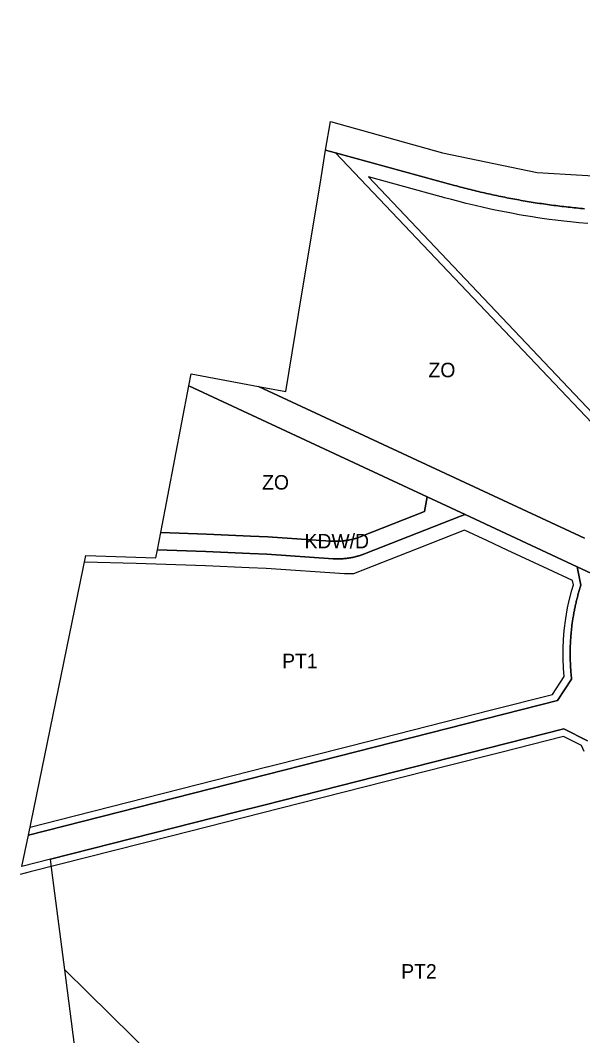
# Model space of a CAD drawing. Extents: x -297746 to -295403, y 27112 to 28877.
# Drawn here: x -297567 to -297178, y 27466 to 28167 of the extents above; entities that cross this region are included whole.
import ezdxf

# ---------------------------------------------------------------- set-up
doc = ezdxf.new("R2010")
doc.units = 0
for name, color, linetype in [('linie_rozgraniczajace', 7, 'Continuous'), ('linie_zabudowy_nieprzekraczalne', 7, 'Continuous'), ('linie_zabudowy_obowiazujace', 7, 'Continuous'), ('oznaczenia_przeznaczen', 7, 'Continuous')]:
    doc.layers.add(name, color=color, linetype=linetype)

msp = doc.modelspace()

# ---------------------------------------------------------------- linework, layer by layer
at = {"layer": 'linie_rozgraniczajace'}
for points in [[(-297352.574, 28097.205), (-297275.154, 28075.397), (-297209.735, 28062.001), (-297116.494, 28056.361), (-297048.036, 28064.682), (-296954.075, 28076.102), (-296853.315, 28078.922), (-296783.197, 28092.318), (-296733.569, 28109.944), (-296648.599, 28167.051)], [(-297176.987, 28036.903), (-297178.41, 28037.03), (-297179.832, 28037.161), (-297181.254, 28037.296), (-297182.676, 28037.435), (-297184.097, 28037.579), (-297185.517, 28037.726), (-297186.938, 28037.877), (-297188.357, 28038.032), (-297189.777, 28038.191), (-297191.196, 28038.354), (-297192.614, 28038.521), (-297194.032, 28038.692), (-297195.45, 28038.867), (-297196.867, 28039.046), (-297198.283, 28039.229), (-297199.699, 28039.416), (-297201.115, 28039.607), (-297202.53, 28039.802), (-297203.944, 28040), (-297205.358, 28040.203), (-297206.771, 28040.41), (-297208.184, 28040.621), (-297209.596, 28040.835), (-297211.007, 28041.054), (-297212.418, 28041.276), (-297213.828, 28041.503), (-297215.238, 28041.733), (-297216.647, 28041.967), (-297218.055, 28042.206), (-297219.463, 28042.448), (-297220.87, 28042.694), (-297222.276, 28042.944), (-297223.681, 28043.198), (-297225.086, 28043.456), (-297226.49, 28043.718), (-297227.894, 28043.984), (-297229.296, 28044.254), (-297230.698, 28044.528), (-297232.099, 28044.805), (-297233.499, 28045.087), (-297234.899, 28045.372), (-297236.297, 28045.662), (-297237.695, 28045.955), (-297239.092, 28046.252), (-297240.488, 28046.553), (-297241.884, 28046.859), (-297243.278, 28047.167), (-297244.672, 28047.48), (-297246.065, 28047.797), (-297247.456, 28048.118), (-297248.847, 28048.442), (-297250.237, 28048.771), (-297251.626, 28049.103), (-297253.015, 28049.439), (-297254.402, 28049.78), (-297255.788, 28050.124), (-297257.173, 28050.471), (-297258.558, 28050.823), (-297259.941, 28051.179), (-297261.323, 28051.538), (-297262.704, 28051.902), (-297264.085, 28052.269), (-297265.464, 28052.64), (-297266.842, 28053.015), (-297348.943, 28075.477), (-297355.848, 28077.366), (-297352.574, 28097.205)], [(-297177, 27809.324), (-297402.243, 27914.223), (-297383.34, 27910.754), (-297372.231, 27978.076), (-297364.965, 28022.112), (-297359.02, 28058.141), (-297355.848, 28077.366), (-297348.943, 28075.477), (-297133.128, 27848.059)], [(-297133.128, 27848.059), (-297348.943, 28075.477), (-297266.842, 28053.015), (-297265.464, 28052.64), (-297264.085, 28052.269), (-297262.704, 28051.902), (-297261.323, 28051.538), (-297259.941, 28051.179), (-297258.558, 28050.823), (-297257.173, 28050.471), (-297255.788, 28050.124), (-297254.402, 28049.78), (-297253.015, 28049.439), (-297251.626, 28049.103), (-297250.237, 28048.771), (-297248.847, 28048.442), (-297247.456, 28048.118), (-297246.065, 28047.797), (-297244.672, 28047.48), (-297243.278, 28047.167), (-297241.884, 28046.859), (-297240.488, 28046.553), (-297239.092, 28046.252), (-297237.695, 28045.955), (-297236.297, 28045.662), (-297234.899, 28045.372), (-297233.499, 28045.087), (-297232.099, 28044.805), (-297230.698, 28044.528), (-297229.296, 28044.254), (-297227.894, 28043.984), (-297226.49, 28043.718), (-297225.086, 28043.456), (-297223.681, 28043.198), (-297222.276, 28042.944), (-297220.87, 28042.694), (-297219.463, 28042.448), (-297218.055, 28042.206), (-297216.647, 28041.967), (-297215.238, 28041.733), (-297213.828, 28041.503), (-297212.418, 28041.276), (-297211.007, 28041.054), (-297209.596, 28040.835), (-297208.184, 28040.621), (-297206.771, 28040.41), (-297205.358, 28040.203), (-297203.944, 28040), (-297202.53, 28039.802), (-297201.115, 28039.607), (-297199.699, 28039.416), (-297198.283, 28039.229), (-297196.867, 28039.046), (-297195.45, 28038.867), (-297194.032, 28038.692), (-297192.614, 28038.521), (-297191.196, 28038.354), (-297189.777, 28038.191), (-297188.357, 28038.032), (-297186.938, 28037.877), (-297185.517, 28037.726), (-297184.097, 28037.579), (-297182.676, 28037.435), (-297181.254, 28037.296), (-297179.832, 28037.161), (-297178.41, 28037.03), (-297176.987, 28036.903)], [(-297152.791, 27775.987), (-297181.991, 27789.586), (-297259.566, 27825.714), (-297285.818, 27837.94), (-297450.331, 27914.556), (-297448.76, 27922.76), (-297402.243, 27914.223), (-297177, 27809.324)], [(-297347.308, 27795.043), (-297347.755, 27795.046), (-297348.202, 27795.052), (-297348.649, 27795.063), (-297349.096, 27795.078), (-297349.543, 27795.096), (-297349.99, 27795.119), (-297350.436, 27795.145), (-297350.68, 27795.161), (-297396.449, 27798.31), (-297408.328, 27798.853), (-297438.575, 27800.185), (-297472.022, 27801.277), (-297469.737, 27813.209), (-297438.115, 27812.176), (-297407.79, 27810.841), (-297395.763, 27810.291), (-297352.553, 27807.318), (-297352.31, 27807.302), (-297351.863, 27807.276), (-297351.416, 27807.253), (-297350.97, 27807.235), (-297350.523, 27807.22), (-297350.076, 27807.21), (-297349.628, 27807.203), (-297349.181, 27807.201), (-297348.734, 27807.202), (-297348.287, 27807.208), (-297347.84, 27807.217), (-297347.393, 27807.23), (-297346.946, 27807.248), (-297346.499, 27807.269), (-297346.053, 27807.295), (-297345.606, 27807.324), (-297345.16, 27807.358), (-297344.715, 27807.395), (-297344.27, 27807.437), (-297343.825, 27807.482), (-297343.38, 27807.531), (-297342.936, 27807.585), (-297342.493, 27807.642), (-297342.05, 27807.703), (-297341.607, 27807.768), (-297341.165, 27807.838), (-297340.724, 27807.911), (-297340.284, 27807.988), (-297339.844, 27808.069), (-297339.405, 27808.154), (-297338.966, 27808.243), (-297338.529, 27808.335), (-297338.092, 27808.432), (-297337.657, 27808.533), (-297337.222, 27808.637), (-297336.788, 27808.746), (-297336.355, 27808.858), (-297335.923, 27808.974), (-297335.492, 27809.094), (-297335.063, 27809.218), (-297334.634, 27809.345), (-297334.206, 27809.477), (-297333.78, 27809.612), (-297333.355, 27809.751), (-297332.931, 27809.894), (-297332.509, 27810.041), (-297332.088, 27810.191), (-297331.668, 27810.346), (-297331.25, 27810.504), (-297330.833, 27810.665), (-297287.504, 27827.693), (-297285.818, 27837.94), (-297259.566, 27825.714), (-297262.647, 27824.569), (-297328.959, 27798.508), (-297329.376, 27798.346), (-297329.795, 27798.188), (-297330.215, 27798.034), (-297330.636, 27797.884), (-297331.058, 27797.737), (-297331.482, 27797.594), (-297331.907, 27797.455), (-297332.333, 27797.32), (-297332.761, 27797.188), (-297333.189, 27797.06), (-297333.619, 27796.937), (-297334.05, 27796.817), (-297334.482, 27796.701), (-297334.915, 27796.588), (-297335.348, 27796.48), (-297335.783, 27796.375), (-297336.219, 27796.275), (-297336.656, 27796.178), (-297337.093, 27796.085), (-297337.531, 27795.996), (-297337.971, 27795.912), (-297338.41, 27795.831), (-297338.851, 27795.753), (-297339.292, 27795.68), (-297339.734, 27795.611), (-297340.176, 27795.546), (-297340.619, 27795.485)], [(-297561.228, 27604.259), (-297521.53, 27797.34), (-297473.092, 27795.69), (-297472.022, 27801.277), (-297438.575, 27800.185), (-297408.328, 27798.853), (-297396.449, 27798.31), (-297350.68, 27795.161), (-297350.436, 27795.145), (-297349.99, 27795.119), (-297349.543, 27795.096), (-297349.096, 27795.078), (-297348.649, 27795.063), (-297348.202, 27795.052), (-297347.755, 27795.046), (-297347.308, 27795.043), (-297346.861, 27795.045), (-297346.414, 27795.05), (-297345.966, 27795.06), (-297345.519, 27795.073), (-297345.073, 27795.091), (-297344.626, 27795.112), (-297344.179, 27795.138), (-297343.733, 27795.167), (-297343.287, 27795.2), (-297342.842, 27795.238), (-297342.396, 27795.279), (-297341.951, 27795.325), (-297341.507, 27795.374), (-297341.063, 27795.427), (-297340.619, 27795.485), (-297340.176, 27795.546), (-297339.734, 27795.611), (-297339.292, 27795.68), (-297338.851, 27795.753), (-297338.41, 27795.831), (-297337.971, 27795.912), (-297337.531, 27795.996), (-297337.093, 27796.085), (-297336.656, 27796.178), (-297336.219, 27796.275), (-297335.783, 27796.375), (-297335.348, 27796.48), (-297334.915, 27796.588), (-297334.482, 27796.701), (-297334.05, 27796.817), (-297333.619, 27796.937), (-297333.189, 27797.06), (-297332.761, 27797.188), (-297332.333, 27797.32), (-297331.907, 27797.455), (-297331.482, 27797.594), (-297331.058, 27797.737), (-297330.636, 27797.884), (-297330.215, 27798.034), (-297329.795, 27798.188), (-297329.376, 27798.346), (-297328.959, 27798.508), (-297262.647, 27824.569), (-297259.566, 27825.714), (-297181.991, 27789.586), (-297179.498, 27776.965), (-297179.736, 27776.217), (-297179.971, 27775.467), (-297180.202, 27774.716), (-297180.429, 27773.963), (-297180.652, 27773.21), (-297180.872, 27772.455), (-297181.088, 27771.7), (-297181.299, 27770.943), (-297181.507, 27770.185), (-297181.711, 27769.426), (-297181.911, 27768.666), (-297182.108, 27767.905), (-297182.3, 27767.144), (-297182.489, 27766.381), (-297182.673, 27765.617), (-297182.854, 27764.852), (-297183.031, 27764.087), (-297183.204, 27763.32), (-297183.373, 27762.553), (-297183.538, 27761.784), (-297183.699, 27761.015), (-297183.857, 27760.245), (-297184.01, 27759.475), (-297184.159, 27758.703), (-297184.305, 27757.931), (-297184.447, 27757.158), (-297184.584, 27756.384), (-297184.718, 27755.61), (-297184.848, 27754.835), (-297184.974, 27754.059), (-297185.096, 27753.283), (-297185.214, 27752.506), (-297185.328, 27751.729), (-297185.438, 27750.951), (-297185.544, 27750.172), (-297185.646, 27749.393), (-297185.744, 27748.613), (-297185.838, 27747.833)], [(-297340.619, 27795.485), (-297341.063, 27795.427), (-297341.507, 27795.374), (-297341.951, 27795.325), (-297342.396, 27795.279), (-297342.842, 27795.238), (-297343.287, 27795.2), (-297343.733, 27795.167), (-297344.179, 27795.138), (-297344.626, 27795.112), (-297345.073, 27795.091), (-297345.519, 27795.073), (-297345.966, 27795.06), (-297346.414, 27795.05), (-297346.861, 27795.045), (-297347.308, 27795.043)], [(-297191.301, 27677.639), (-297398.591, 27624.957), (-297418.041, 27620.014), (-297545.905, 27587.518), (-297565.705, 27582.486), (-297561.228, 27604.259), (-297195.737, 27697.147), (-297185.88, 27711.971), (-297185.946, 27712.549), (-297186.031, 27713.33), (-297186.112, 27714.112), (-297186.19, 27714.894), (-297186.263, 27715.676), (-297186.333, 27716.459), (-297186.398, 27717.242), (-297186.46, 27718.025), (-297186.518, 27718.809), (-297186.571, 27719.593), (-297186.621, 27720.377), (-297186.666, 27721.162), (-297186.708, 27721.946), (-297186.745, 27722.731), (-297186.779, 27723.516), (-297186.809, 27724.302), (-297186.834, 27725.087), (-297186.856, 27725.872), (-297186.873, 27726.658), (-297186.887, 27727.444), (-297186.897, 27728.23), (-297186.902, 27729.015), (-297186.904, 27729.801), (-297186.902, 27730.587), (-297186.895, 27731.373), (-297186.885, 27732.158), (-297186.87, 27732.944), (-297186.852, 27733.73), (-297186.83, 27734.515), (-297186.803, 27735.301), (-297186.773, 27736.086), (-297186.738, 27736.871), (-297186.7, 27737.656), (-297186.658, 27738.44), (-297186.611, 27739.225), (-297186.561, 27740.009), (-297186.507, 27740.793), (-297186.448, 27741.577), (-297186.386, 27742.36), (-297186.32, 27743.143), (-297186.249, 27743.926), (-297186.175, 27744.708), (-297186.097, 27745.49), (-297186.014, 27746.271), (-297185.928, 27747.052), (-297185.838, 27747.833), (-297185.744, 27748.613), (-297185.646, 27749.393), (-297185.544, 27750.172), (-297185.438, 27750.951), (-297185.328, 27751.729), (-297185.214, 27752.506), (-297185.096, 27753.283), (-297184.974, 27754.059), (-297184.848, 27754.835), (-297184.718, 27755.61), (-297184.584, 27756.384), (-297184.447, 27757.158), (-297184.305, 27757.931), (-297184.159, 27758.703), (-297184.01, 27759.475), (-297183.857, 27760.245), (-297183.699, 27761.015), (-297183.538, 27761.784), (-297183.373, 27762.553), (-297183.204, 27763.32), (-297183.031, 27764.087), (-297182.854, 27764.852), (-297182.673, 27765.617), (-297182.489, 27766.381), (-297182.3, 27767.144), (-297182.108, 27767.905), (-297181.911, 27768.666), (-297181.711, 27769.426), (-297181.507, 27770.185), (-297181.299, 27770.943), (-297181.088, 27771.7), (-297180.872, 27772.455), (-297180.652, 27773.21), (-297180.429, 27773.963), (-297180.202, 27774.716), (-297179.971, 27775.467), (-297179.736, 27776.217), (-297179.498, 27776.965), (-297181.991, 27789.586), (-297152.791, 27775.987)], [(-297185.838, 27747.833), (-297185.928, 27747.052), (-297186.014, 27746.271), (-297186.097, 27745.49), (-297186.175, 27744.708), (-297186.249, 27743.926), (-297186.32, 27743.143), (-297186.386, 27742.36), (-297186.448, 27741.577), (-297186.507, 27740.793), (-297186.561, 27740.009), (-297186.611, 27739.225), (-297186.658, 27738.44), (-297186.7, 27737.656), (-297186.738, 27736.871), (-297186.773, 27736.086), (-297186.803, 27735.301), (-297186.83, 27734.515), (-297186.852, 27733.73), (-297186.87, 27732.944), (-297186.885, 27732.158), (-297186.895, 27731.373), (-297186.902, 27730.587), (-297186.904, 27729.801), (-297186.902, 27729.015), (-297186.897, 27728.23), (-297186.887, 27727.444), (-297186.873, 27726.658), (-297186.856, 27725.872), (-297186.834, 27725.087), (-297186.809, 27724.302), (-297186.779, 27723.516), (-297186.745, 27722.731), (-297186.708, 27721.946), (-297186.666, 27721.162), (-297186.621, 27720.377), (-297186.571, 27719.593), (-297186.518, 27718.809), (-297186.46, 27718.025), (-297186.398, 27717.242), (-297186.333, 27716.459), (-297186.263, 27715.676), (-297186.19, 27714.894), (-297186.112, 27714.112), (-297186.031, 27713.33), (-297185.946, 27712.549), (-297185.88, 27711.971), (-297195.737, 27697.147), (-297561.228, 27604.259)], [(-297379.62, 27357.248), (-297536.097, 27511.179), (-297544.93, 27579.93), (-297545.905, 27587.518), (-297418.041, 27620.014), (-297398.591, 27624.957), (-297191.301, 27677.639), (-297175.004, 27669.361)], [(-297175.004, 27669.361), (-297191.301, 27677.639)]]:
    msp.add_lwpolyline(points, dxfattribs=at)
for points in [[(-297349.181, 27807.201), (-297349.628, 27807.203), (-297350.076, 27807.21), (-297350.523, 27807.22), (-297350.97, 27807.235), (-297351.416, 27807.253), (-297351.863, 27807.276), (-297352.31, 27807.302), (-297352.553, 27807.318), (-297395.763, 27810.291), (-297407.79, 27810.841), (-297438.115, 27812.176), (-297469.737, 27813.209), (-297450.331, 27914.556), (-297285.818, 27837.94), (-297287.504, 27827.693), (-297330.833, 27810.665), (-297331.25, 27810.504), (-297331.668, 27810.346), (-297332.088, 27810.191), (-297332.509, 27810.041), (-297332.931, 27809.894), (-297333.355, 27809.751), (-297333.78, 27809.612), (-297334.206, 27809.477), (-297334.634, 27809.345), (-297335.063, 27809.218), (-297335.492, 27809.094), (-297335.923, 27808.974), (-297336.355, 27808.858), (-297336.788, 27808.746), (-297337.222, 27808.637), (-297337.657, 27808.533), (-297338.092, 27808.432), (-297338.529, 27808.335), (-297338.966, 27808.243), (-297339.405, 27808.154), (-297339.844, 27808.069), (-297340.284, 27807.988), (-297340.724, 27807.911), (-297341.165, 27807.838), (-297341.607, 27807.768), (-297342.05, 27807.703), (-297342.493, 27807.642), (-297342.936, 27807.585), (-297343.38, 27807.531), (-297343.825, 27807.482), (-297344.27, 27807.437), (-297344.715, 27807.395), (-297345.16, 27807.358), (-297345.606, 27807.324), (-297346.053, 27807.295), (-297346.499, 27807.269), (-297346.946, 27807.248), (-297347.393, 27807.23), (-297347.84, 27807.217), (-297348.287, 27807.208), (-297348.734, 27807.202)], [(-297215.315, 27280.215), (-297256.262, 27299.118), (-297370.123, 27306.524), (-297400.878, 27308.022), (-297525.782, 27430.894), (-297536.097, 27511.179), (-297379.62, 27357.248), (-297243.742, 27348.41), (-297194.759, 27325.796), (-297200.803, 27312.318)]]:
    msp.add_lwpolyline(points, close=True, dxfattribs=at)
at = {"layer": 'linie_zabudowy_nieprzekraczalne'}
for points in [[(-297326.341, 28058.929), (-297167.124, 27891.151)], [(-297326.341, 28058.929), (-297167.124, 27891.151)], [(-297174.593, 28026.666), (-297180.884, 28027.218), (-297186.661, 28027.793), (-297191.377, 28028.311), (-297196.969, 28028.982), (-297201.428, 28029.561), (-297207.967, 28030.481), (-297214.429, 28031.473), (-297219.318, 28032.279), (-297222.13, 28032.765), (-297227.506, 28033.737), (-297233.644, 28034.919), (-297239.79, 28036.18), (-297246.759, 28037.703), (-297252.451, 28039.021), (-297258.866, 28040.588), (-297264.458, 28042.025), (-297268.896, 28043.213), (-297273.644, 28044.53), (-297275.754, 28045.131), (-297276.085, 28045.179), (-297326.341, 28058.929)], [(-297230.542, 27801.169), (-297244.109, 27807.488), (-297259.973, 27814.876), (-297292.548, 27802.074), (-297336.572, 27784.772), (-297342.936, 27784.607), (-297397.017, 27788.328), (-297408.773, 27788.865), (-297438.955, 27790.194), (-297486.716, 27791.753), (-297522.451, 27792.85)], [(-297560.106, 27609.705), (-297540.12, 27614.784), (-297396.415, 27651.306), (-297396.26, 27651.346), (-297338.79, 27665.951), (-297242.21, 27690.496)], [(-297235.783, 27661.176), (-297272.33, 27651.888), (-297328.649, 27637.575), (-297387.499, 27622.618), (-297462.51, 27603.555), (-297560.033, 27578.769), (-297566.821, 27577.044)]]:
    msp.add_lwpolyline(points, dxfattribs=at)
at = {"layer": 'linie_zabudowy_obowiazujace'}
for points in [[(-297242.21, 27690.496), (-297199.043, 27701.467), (-297191.033, 27713.708), (-297191.546, 27719.636), (-297191.805, 27726.149), (-297191.79, 27733.246), (-297191.525, 27739.436), (-297191.04, 27745.46), (-297189.979, 27753.9), (-297188.702, 27761.165), (-297187.616, 27766.218), (-297185.788, 27773.357), (-297184.634, 27777.182), (-297185.21, 27780.097), (-297202.023, 27787.887), (-297230.542, 27801.169)], [(-297177.221, 27661.902), (-297178.979, 27666.035), (-297191.48, 27672.436), (-297235.783, 27661.176)]]:
    msp.add_lwpolyline(points, dxfattribs=at)

# ---------------------------------------------------------------- texts
at = {"layer": 'oznaczenia_przeznaczen'}
for s, p in [('ZO', (-297284.792, 27920.509)), ('ZO', (-297399.75, 27842.923)), ('KDW/D', (-297370.418, 27802.318)), ('PT1', (-297385.91, 27719.547)), ('PT2', (-297303.646, 27505.1))]:
    msp.add_text(s, height=10, dxfattribs=at).set_placement(p)

doc.saveas('drawing.dxf')
